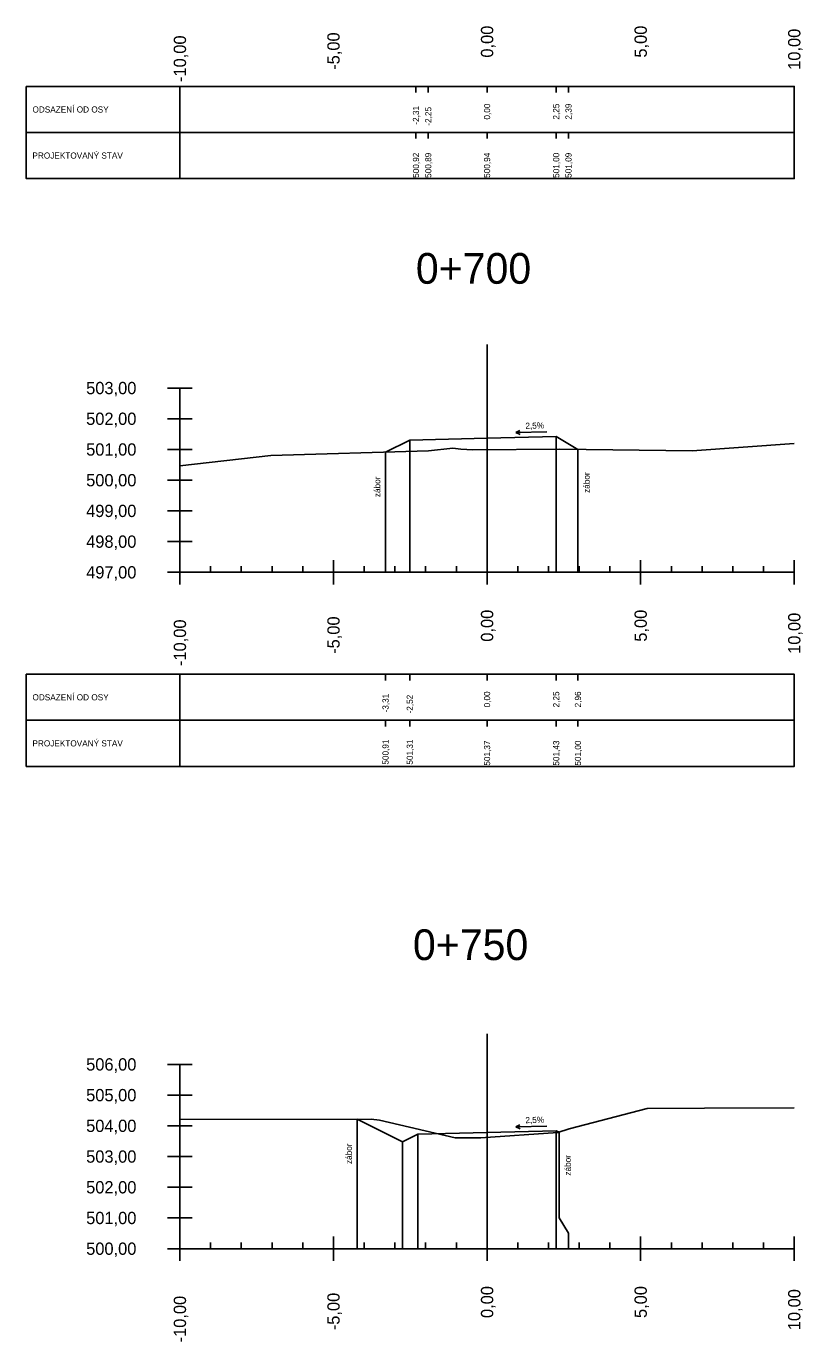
# Model space of a CAD drawing. Extents: x -631407 to -631215, y -1089700 to -1088598.
# Drawn here: x -631373.74 to -631348.47, y -1088900.41 to -1088857.58 of the extents above; entities that cross this region are included whole.
import ezdxf

# ---------------------------------------------------------------- set-up
doc = ezdxf.new("R2010")
doc.units = 0
for name, color, linetype in [('59', 7, 'Continuous'), ('NIVELETA_VYSKY', 7, 'Continuous'), ('REZ_BODY', 7, 'Continuous'), ('REZ_ODSTUPY', 7, 'Continuous'), ('REZ_POPIS', 7, 'Continuous'), ('REZ_RAMY', 7, 'Continuous'), ('REZ_STANICENI', 7, 'Continuous'), ('REZ_SVISLE', 7, 'Continuous'), ('REZ_TENKA', 7, 'Continuous'), ('REZ_TLUSTA', 7, 'Continuous'), ('TABULKA_POPIS', 7, 'Continuous'), ('TEREN', 7, 'Continuous'), ('zábor', 7, 'Continuous')]:
    doc.layers.add(name, color=color, linetype=linetype)

msp = doc.modelspace()

# ---------------------------------------------------------------- linework, layer by layer
at = {"layer": '59'}
for p, q in [((-631369.144, -1088869.359), (-631368.344, -1088869.359)), ((-631368.744, -1088869.359), (-631368.744, -1088875.359)), ((-631369.144, -1088870.359), (-631368.344, -1088870.359)), ((-631369.144, -1088871.359), (-631368.344, -1088871.359)), ((-631369.144, -1088872.359), (-631368.344, -1088872.359)), ((-631369.144, -1088873.359), (-631368.344, -1088873.359)), ((-631369.144, -1088874.359), (-631368.344, -1088874.359)), ((-631369.144, -1088875.359), (-631368.344, -1088875.359)), ((-631369.144, -1088891.381), (-631368.344, -1088891.381)), ((-631368.744, -1088891.381), (-631368.744, -1088897.381)), ((-631369.144, -1088892.381), (-631368.344, -1088892.381)), ((-631369.144, -1088893.381), (-631368.344, -1088893.381)), ((-631369.144, -1088894.381), (-631368.344, -1088894.381)), ((-631369.144, -1088895.381), (-631368.344, -1088895.381)), ((-631369.144, -1088896.381), (-631368.344, -1088896.381)), ((-631369.144, -1088897.381), (-631368.344, -1088897.381))]:
    msp.add_line(p, q, dxfattribs=at)
at = {"layer": 'REZ_RAMY'}
for p, q in [((-631373.744, -1088859.539), (-631373.744, -1088862.539)), ((-631368.744, -1088859.539), (-631368.744, -1088862.539)), ((-631368.744, -1088859.739), (-631368.744, -1088859.539)), ((-631361.059, -1088859.739), (-631361.059, -1088859.539)), ((-631360.659, -1088859.739), (-631360.659, -1088859.539)), ((-631358.744, -1088859.739), (-631358.744, -1088859.539)), ((-631356.494, -1088859.739), (-631356.494, -1088859.539)), ((-631356.094, -1088859.739), (-631356.094, -1088859.539)), ((-631373.744, -1088861.039), (-631348.744, -1088861.039)), ((-631368.744, -1088861.239), (-631368.744, -1088861.039)), ((-631361.059, -1088861.239), (-631361.059, -1088861.039)), ((-631360.659, -1088861.239), (-631360.659, -1088861.039)), ((-631358.744, -1088861.239), (-631358.744, -1088861.039)), ((-631356.494, -1088861.239), (-631356.494, -1088861.039)), ((-631356.094, -1088861.239), (-631356.094, -1088861.039)), ((-631373.744, -1088878.678), (-631373.744, -1088881.678)), ((-631368.744, -1088878.678), (-631368.744, -1088881.678)), ((-631362.05, -1088878.878), (-631362.05, -1088878.678)), ((-631361.261, -1088878.878), (-631361.261, -1088878.678)), ((-631358.744, -1088878.878), (-631358.744, -1088878.678)), ((-631356.494, -1088878.878), (-631356.494, -1088878.678)), ((-631355.786, -1088878.878), (-631355.786, -1088878.678)), ((-631373.744, -1088880.178), (-631348.744, -1088880.178)), ((-631362.05, -1088880.378), (-631362.05, -1088880.178)), ((-631361.261, -1088880.378), (-631361.261, -1088880.178)), ((-631358.744, -1088880.378), (-631358.744, -1088880.178)), ((-631356.494, -1088880.378), (-631356.494, -1088880.178)), ((-631355.786, -1088880.378), (-631355.786, -1088880.178))]:
    msp.add_line(p, q, dxfattribs=at)
for points in [[(-631373.744, -1088859.539), (-631373.744, -1088862.539), (-631348.744, -1088862.539), (-631348.744, -1088859.539)], [(-631373.744, -1088878.678), (-631373.744, -1088881.678), (-631348.744, -1088881.678), (-631348.744, -1088878.678)]]:
    msp.add_lwpolyline(points, close=True, dxfattribs=at)
at = {"layer": 'REZ_SVISLE'}
for points in [[(-631361.261, -1088871.053), (-631361.261, -1088874.359), (-631361.261, -1088874.859), (-631361.261, -1088875.359)], [(-631358.744, -1088870.99), (-631358.744, -1088874.359), (-631358.744, -1088874.859), (-631358.744, -1088875.359)], [(-631356.494, -1088870.933), (-631356.494, -1088874.359), (-631356.494, -1088874.859), (-631356.494, -1088875.359)], [(-631362.05, -1088871.447), (-631362.05, -1088874.359), (-631362.05, -1088874.859), (-631362.05, -1088875.359)], [(-631355.786, -1088871.358), (-631355.786, -1088874.359), (-631355.786, -1088874.859), (-631355.786, -1088875.359)], [(-631362.975, -1088893.162), (-631362.975, -1088896.381), (-631362.975, -1088896.881), (-631362.975, -1088897.381)], [(-631361.494, -1088893.902), (-631361.494, -1088896.381), (-631361.494, -1088896.881), (-631361.494, -1088897.381)], [(-631360.994, -1088893.652), (-631360.994, -1088896.381), (-631360.994, -1088896.881), (-631360.994, -1088897.381)], [(-631358.744, -1088893.596), (-631358.744, -1088896.381), (-631358.744, -1088896.881), (-631358.744, -1088897.381)], [(-631356.494, -1088893.54), (-631356.494, -1088896.381), (-631356.494, -1088896.881), (-631356.494, -1088897.381)], [(-631356.4, -1088893.587), (-631356.4, -1088896.381), (-631356.094, -1088896.881), (-631356.094, -1088897.381)]]:
    msp.add_lwpolyline(points, dxfattribs=at)
at = {"layer": 'REZ_TENKA'}
for p, q in [((-631367.744, -1088875.359), (-631367.744, -1088875.159)), ((-631366.744, -1088875.359), (-631366.744, -1088875.159)), ((-631365.744, -1088875.359), (-631365.744, -1088875.159)), ((-631364.744, -1088875.359), (-631364.744, -1088875.159)), ((-631362.744, -1088875.359), (-631362.744, -1088875.159)), ((-631361.744, -1088875.359), (-631361.744, -1088875.159)), ((-631360.744, -1088875.359), (-631360.744, -1088875.159)), ((-631359.744, -1088875.359), (-631359.744, -1088875.159)), ((-631357.744, -1088875.359), (-631357.744, -1088875.159)), ((-631356.744, -1088875.359), (-631356.744, -1088875.159)), ((-631355.744, -1088875.359), (-631355.744, -1088875.159)), ((-631354.744, -1088875.359), (-631354.744, -1088875.159)), ((-631352.744, -1088875.359), (-631352.744, -1088875.159)), ((-631351.744, -1088875.359), (-631351.744, -1088875.159)), ((-631350.744, -1088875.359), (-631350.744, -1088875.159)), ((-631349.744, -1088875.359), (-631349.744, -1088875.159)), ((-631367.744, -1088897.381), (-631367.744, -1088897.181)), ((-631366.744, -1088897.381), (-631366.744, -1088897.181)), ((-631365.744, -1088897.381), (-631365.744, -1088897.181)), ((-631364.744, -1088897.381), (-631364.744, -1088897.181)), ((-631362.744, -1088897.381), (-631362.744, -1088897.181)), ((-631361.744, -1088897.381), (-631361.744, -1088897.181)), ((-631360.744, -1088897.381), (-631360.744, -1088897.181)), ((-631359.744, -1088897.381), (-631359.744, -1088897.181)), ((-631357.744, -1088897.381), (-631357.744, -1088897.181)), ((-631356.744, -1088897.381), (-631356.744, -1088897.181)), ((-631355.744, -1088897.381), (-631355.744, -1088897.181)), ((-631354.744, -1088897.381), (-631354.744, -1088897.181)), ((-631352.744, -1088897.381), (-631352.744, -1088897.181)), ((-631351.744, -1088897.381), (-631351.744, -1088897.181)), ((-631350.744, -1088897.381), (-631350.744, -1088897.181)), ((-631349.744, -1088897.381), (-631349.744, -1088897.181))]:
    msp.add_line(p, q, dxfattribs=at)
at = {"layer": 'REZ_TLUSTA'}
for p, q in [((-631358.744, -1088867.939), (-631358.744, -1088875.359)), ((-631368.744, -1088875.759), (-631368.744, -1088874.959)), ((-631363.744, -1088875.759), (-631363.744, -1088874.959)), ((-631358.744, -1088875.759), (-631358.744, -1088874.959)), ((-631353.744, -1088875.759), (-631353.744, -1088874.959)), ((-631348.744, -1088875.759), (-631348.744, -1088874.959)), ((-631368.744, -1088875.359), (-631348.744, -1088875.359)), ((-631358.744, -1088890.381), (-631358.744, -1088897.381)), ((-631368.744, -1088897.781), (-631368.744, -1088896.981)), ((-631368.744, -1088897.381), (-631348.744, -1088897.381)), ((-631363.744, -1088897.781), (-631363.744, -1088896.981)), ((-631358.744, -1088897.781), (-631358.744, -1088896.981)), ((-631353.744, -1088897.781), (-631353.744, -1088896.981)), ((-631348.744, -1088897.781), (-631348.744, -1088896.981))]:
    msp.add_line(p, q, dxfattribs=at)
at = {"layer": 'TEREN'}
for points in [[(-631368.744, -1088871.891), (-631365.782, -1088871.56), (-631360.65, -1088871.405), (-631359.859, -1088871.32), (-631359.598, -1088871.353), (-631359.203, -1088871.368), (-631356.378, -1088871.352), (-631352.066, -1088871.4), (-631348.744, -1088871.162)], [(-631362.05, -1088871.447), (-631361.261, -1088871.053), (-631358.744, -1088870.99), (-631356.494, -1088870.933), (-631355.786, -1088871.358)], [(-631368.744, -1088893.18), (-631362.517, -1088893.16), (-631362.248, -1088893.193), (-631359.779, -1088893.772), (-631358.942, -1088893.768), (-631356.444, -1088893.601), (-631356.07, -1088893.475), (-631353.527, -1088892.814), (-631351.662, -1088892.807), (-631348.744, -1088892.79)], [(-631362.975, -1088893.162), (-631361.494, -1088893.902), (-631360.994, -1088893.652), (-631358.744, -1088893.596), (-631356.494, -1088893.54), (-631356.4, -1088893.587)]]:
    msp.add_lwpolyline(points, dxfattribs=at)
at = {"layer": 'zábor'}
for p, q in [((-631357.811, -1088870.81), (-631357.674, -1088870.746)), ((-631357.811, -1088870.81), (-631356.803, -1088870.785)), ((-631357.811, -1088870.81), (-631357.671, -1088870.868)), ((-631357.811, -1088893.417), (-631357.674, -1088893.352)), ((-631357.811, -1088893.417), (-631356.803, -1088893.391)), ((-631357.811, -1088893.417), (-631357.671, -1088893.474))]:
    msp.add_line(p, q, dxfattribs=at)

# ---------------------------------------------------------------- texts
at = {"layer": 'NIVELETA_VYSKY'}
for s, p in [('500,92', (-631360.959, -1088862.515)), ('500,89', (-631360.559, -1088862.515)), ('500,94', (-631358.644, -1088862.515)), ('501,00', (-631356.394, -1088862.515)), ('501,09', (-631355.994, -1088862.515)), ('500,91', (-631361.95, -1088881.621)), ('501,31', (-631361.161, -1088881.621)), ('501,37', (-631358.644, -1088881.654)), ('501,43', (-631356.394, -1088881.654)), ('501,00', (-631355.686, -1088881.654))]:
    msp.add_text(s, height=0.2, rotation=90, dxfattribs=at).set_placement(p)
at = {"layer": 'REZ_BODY'}
for s, p in [('0,00', (-631358.644, -1088860.618)), ('2,25', (-631356.394, -1088860.618)), ('2,39', (-631355.994, -1088860.618)), ('-2,31', (-631360.959, -1088860.783)), ('-2,25', (-631360.559, -1088860.816)), ('-3,31', (-631361.95, -1088879.922)), ('-2,52', (-631361.161, -1088879.955)), ('0,00', (-631358.644, -1088879.757)), ('2,25', (-631356.394, -1088879.757)), ('2,96', (-631355.686, -1088879.757))]:
    msp.add_text(s, height=0.2, rotation=90, dxfattribs=at).set_placement(p)
at = {"layer": 'REZ_ODSTUPY'}
for s, p in [('-10,00', (-631368.544, -1088859.395)), ('-5,00', (-631363.544, -1088858.998)), ('0,00', (-631358.544, -1088858.601)), ('5,00', (-631353.544, -1088858.601)), ('10,00', (-631348.544, -1088858.998)), ('-5,00', (-631363.544, -1088878.014)), ('0,00', (-631358.544, -1088877.618)), ('5,00', (-631353.544, -1088877.618)), ('10,00', (-631348.544, -1088878.014)), ('-10,00', (-631368.544, -1088878.411)), ('0,00', (-631358.544, -1088899.639)), ('5,00', (-631353.544, -1088899.639)), ('-10,00', (-631368.544, -1088900.433)), ('-5,00', (-631363.544, -1088900.036)), ('10,00', (-631348.544, -1088900.036))]:
    msp.add_text(s, height=0.4, rotation=90, dxfattribs=at).set_placement(p)
at = {"layer": 'REZ_POPIS'}
for s, p in [('503,00', (-631371.796, -1088869.559)), ('502,00', (-631371.796, -1088870.559)), ('501,00', (-631371.796, -1088871.559)), ('500,00', (-631371.796, -1088872.559)), ('499,00', (-631371.796, -1088873.559)), ('498,00', (-631371.796, -1088874.559)), ('497,00', (-631371.796, -1088875.559)), ('506,00', (-631371.796, -1088891.581)), ('505,00', (-631371.796, -1088892.581)), ('504,00', (-631371.796, -1088893.581)), ('503,00', (-631371.796, -1088894.581)), ('502,00', (-631371.796, -1088895.581)), ('501,00', (-631371.796, -1088896.581)), ('500,00', (-631371.796, -1088897.581))]:
    msp.add_text(s, height=0.4, dxfattribs=at).set_placement(p)
at = {"layer": 'REZ_STANICENI'}
for s, p in [('0+700', (-631361.063, -1088865.963)), ('0+750', (-631361.158, -1088887.984))]:
    msp.add_text(s, height=1, dxfattribs=at).set_placement(p)
at = {"layer": 'TABULKA_POPIS'}
for s, p in [('ODSAZENÍ OD OSY', (-631373.544, -1088860.389)), ('PROJEKTOVANÝ STAV', (-631373.544, -1088861.889)), ('ODSAZENÍ OD OSY', (-631373.544, -1088879.528)), ('PROJEKTOVANÝ STAV', (-631373.544, -1088881.028))]:
    msp.add_text(s, height=0.2, dxfattribs=at).set_placement(p)
at = {"layer": 'zábor'}
for s, rotation, p in [('2,5%', 1.4321, (-631357.494, -1088870.689)), ('zábor', 90, (-631355.403, -1088872.773)), ('zábor', 90, (-631362.22, -1088872.911)), ('2,5%', 1.4321, (-631357.494, -1088893.296)), ('zábor', 90, (-631363.145, -1088894.625)), ('zábor', 90, (-631356.018, -1088895.001))]:
    msp.add_text(s, height=0.2, rotation=rotation, dxfattribs=at).set_placement(p)

doc.saveas('drawing.dxf')
